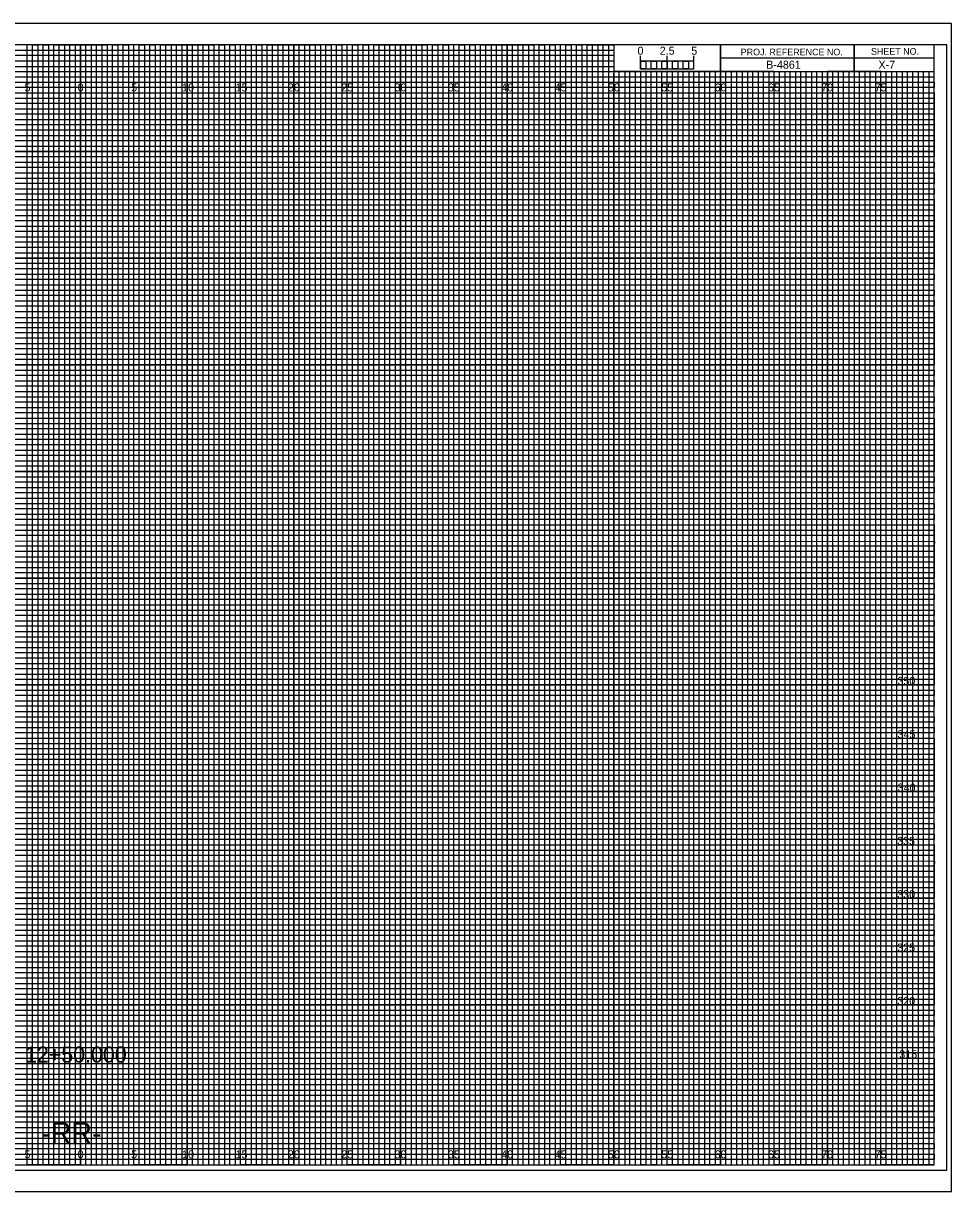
# Model space of a CAD drawing. Extents: x -7 to 162, y -2 to 327.
# Drawn here: x 74.6 to 161.7, y 217.5 to 327 of the extents above; entities that cross this region are included whole.
import ezdxf

# ---------------------------------------------------------------- set-up
doc = ezdxf.new("R2010")
doc.units = 0
for name, color, linetype in [('Exist Cross Section Cell', 7, 'Continuous'), ('Exist XS Center Line Elevation Label', 7, 'Continuous'), ('Exist XS Ground Line', 7, 'Continuous'), ('Old_Level_1', 7, 'Continuous'), ('Prop Retaining Wall', 7, 'Continuous'), ('Prop XS Bar Scale Labels', 7, 'Continuous'), ('Prop XS Bridge', 7, 'Continuous'), ('Prop XS Ditch Standard Text', 7, 'Continuous'), ('Prop XS EOT Tick Mark', 7, 'Continuous'), ('Prop XS Finish Grade Concrete', 7, 'Continuous'), ('Prop XS Finish Grade Earthwork', 7, 'Continuous'), ('Prop XS Label Text', 7, 'Continuous'), ('Prop XS SS Elevation Text', 7, 'Continuous'), ('Prop XS Subgrade', 7, 'Continuous'), ('Scratch_Level_3', 7, 'Continuous'), ('Scratch_Level_4', 7, 'Continuous'), ('Typical Arrow Superelevation CELL', 7, 'Continuous')]:
    doc.layers.add(name, color=color, linetype=linetype)

msp = doc.modelspace()

# ---------------------------------------------------------------- linework, layer by layer
at = {"layer": 'Exist XS Center Line Elevation Label'}
for points in [[(72.5, 220), (77.5, 220), (77.5, 325), (82.5, 325), (82.5, 220), (87.5, 220), (87.5, 325), (92.5, 325), (92.5, 220), (97.5, 220), (97.5, 325), (102.5, 325), (102.5, 220), (107.5, 220), (107.5, 325), (112.5, 325), (112.5, 220), (117.5, 220), (117.5, 325), (122.5, 325), (122.5, 220), (127.5, 220), (127.5, 325), (129.97, 325), (130, 325), (130, 322.5), (132.5, 322.5), (132.5, 220), (137.5, 220), (137.5, 322.5), (142.5, 322.5), (142.5, 220), (147.5, 220), (147.5, 322.5), (152.5, 322.5), (152.5, 220), (157.5, 220), (157.5, 322.5)], [(0, 322.5), (137.5, 322.5)], [(0, 312.5), (160, 312.5), (160, 317.5), (0, 317.5)], [(0, 302.5), (160, 302.5), (160, 307.5), (0, 307.5)], [(0, 292.5), (160, 292.5), (160, 297.5), (0, 297.5)], [(0, 282.5), (160, 282.5), (160, 287.5), (0, 287.5)], [(0, 272.5), (160, 272.5), (160, 277.5), (0, 277.5)], [(0, 262.5), (160, 262.5), (160, 267.5), (0, 267.5)], [(0, 252.5), (160, 252.5), (160, 257.5), (0, 257.5)], [(0, 242.5), (160, 242.5), (160, 247.5), (0, 247.5)], [(0, 232.5), (160, 232.5), (160, 237.5), (0, 237.5)], [(0, 222.5), (160, 222.5), (160, 227.5), (0, 227.5)]]:
    msp.add_lwpolyline(points, dxfattribs=at)
at = {"layer": 'Exist XS Ground Line'}
for p, q in [((75, 325), (70, 325)), ((75, 220), (75, 325)), ((85, 325), (80, 325)), ((80, 325), (80, 220)), ((85, 220), (85, 325)), ((95, 325), (90, 325)), ((90, 325), (90, 220)), ((95, 220), (95, 325)), ((105, 325), (100, 325)), ((100, 325), (100, 220)), ((105, 220), (105, 325)), ((115, 325), (110, 325)), ((110, 325), (110, 220)), ((115, 220), (115, 325)), ((125, 325), (120, 325)), ((120, 325), (120, 220)), ((125, 220), (125, 325)), ((130, 325), (130, 220)), ((135, 220), (135, 322.5)), ((145, 322.5), (140, 322.5)), ((140, 322.5), (140, 220)), ((145, 220), (145, 322.5)), ((155, 322.5), (150, 322.5)), ((150, 322.5), (150, 220)), ((155, 220), (155, 322.5)), ((80, 220), (75, 220)), ((90, 220), (85, 220)), ((100, 220), (95, 220)), ((110, 220), (105, 220)), ((120, 220), (115, 220)), ((130, 220), (125, 220)), ((140, 220), (135, 220)), ((150, 220), (145, 220)), ((160, 220), (155, 220)), ((160, 220), (160, 220))]:
    msp.add_line(p, q, dxfattribs=at)
for points in [[(0, 320), (160, 320), (160, 315), (0, 315)], [(0, 310), (160, 310), (160, 305), (0, 305)], [(0, 300), (160, 300), (160, 295), (0, 295)], [(0, 290), (160, 290), (160, 285), (0, 285)], [(0, 280), (160, 280), (160, 275), (0, 275)], [(0, 270), (160, 270), (160, 265), (0, 265)], [(0, 260), (160, 260), (160, 255), (0, 255)], [(0, 250), (160, 250), (160, 245), (0, 245)], [(0, 240), (160, 240), (160, 235), (0, 235)], [(0, 230), (160, 230), (160, 225), (0, 225)]]:
    msp.add_lwpolyline(points, dxfattribs=at)
at = {"layer": 'Old_Level_1'}
msp.add_lwpolyline([(-5.4, 219.5), (161.2, 219.5), (161.2, 325), (-5.4, 325)], close=True, dxfattribs=at)
at = {"layer": 'Prop XS Bridge'}
for p, q in [((75, 220), (75, 325)), ((80, 220), (80, 325)), ((85, 220), (85, 325)), ((90, 220), (90, 325)), ((95, 220), (95, 325)), ((100, 220), (100, 325)), ((105, 220), (105, 325)), ((110, 220), (110, 325)), ((115, 220), (115, 325)), ((120, 220), (120, 325)), ((125, 220), (125, 325)), ((130, 220), (130, 322.34)), ((135, 220), (135, 322.34)), ((140, 220), (140, 322.34)), ((145, 220), (145, 322.34)), ((150, 220), (150, 322.34)), ((155, 220), (155, 322.34)), ((0, 320), (160, 320)), ((0, 315), (160, 315)), ((0, 310), (160, 310)), ((0, 305), (160, 305)), ((0, 300), (160, 300)), ((0, 295), (160, 295)), ((0, 290), (160, 290)), ((0, 285), (160, 285)), ((0, 280), (160, 280)), ((0, 275), (160, 275)), ((0, 270), (160, 270)), ((0, 265), (160, 265)), ((0, 260), (160, 260)), ((0, 255), (160, 255)), ((0, 250), (160, 250)), ((0, 245), (160, 245)), ((0, 240), (160, 240)), ((0, 235), (160, 235)), ((0, 230), (160, 230)), ((0, 225), (160, 225))]:
    msp.add_line(p, q, dxfattribs=at)
at = {"layer": 'Prop XS EOT Tick Mark'}
for p, q in [((152.5, 325), (152.5, 322.5)), ((152.5, 322.5), (152.5, 325)), ((160, 323.75), (140, 323.75)), ((140, 323.75), (140, 322.5)), ((140, 322.5), (160, 322.5))]:
    msp.add_line(p, q, dxfattribs=at)
for points in [[(160, 325), (0, 325), (0, 220), (160, 220)], [(140, 325), (130, 325), (130, 322.51), (140, 322.51)], [(160, 325), (140, 325), (140, 322.5), (160, 322.5)]]:
    msp.add_lwpolyline(points, close=True, dxfattribs=at)
at = {"layer": 'Prop XS Finish Grade Earthwork'}
for p, q in [((161.65, 327), (-6.7, 327)), ((-6.7, 217.5), (161.65, 217.5))]:
    msp.add_line(p, q, dxfattribs=at)
at = {"layer": 'Prop XS Label Text'}
for p, q in [((133.5, 322.5), (133, 322.5)), ((133, 322.5), (133, 220)), ((133.5, 220), (133.5, 322.5)), ((134.5, 322.5), (134, 322.5)), ((134, 322.5), (134, 220)), ((134.5, 220), (134.5, 322.5)), ((133, 220), (132.5, 220)), ((134, 220), (133.5, 220))]:
    msp.add_line(p, q, dxfattribs=at)
for points in [[(75, 220), (75.5, 220), (75.5, 325), (76, 325), (76, 220)], [(76, 220), (76.5, 220), (76.5, 325), (77, 325), (77, 220)], [(77.5, 220), (78, 220), (78, 325), (78.5, 325), (78.5, 220)], [(78.5, 220), (79, 220), (79, 325), (79.5, 325), (79.5, 220)], [(80, 220), (80.5, 220), (80.5, 325), (81, 325), (81, 220)], [(81, 220), (81.5, 220), (81.5, 325), (82, 325), (82, 220)], [(82.5, 220), (83, 220), (83, 325), (83.5, 325), (83.5, 220)], [(83.5, 220), (84, 220), (84, 325), (84.5, 325), (84.5, 220)], [(85, 220), (85.5, 220), (85.5, 325), (86, 325), (86, 220)], [(86, 220), (86.5, 220), (86.5, 325), (87, 325), (87, 220)], [(87.5, 220), (88, 220), (88, 325), (88.5, 325), (88.5, 220)], [(88.5, 220), (89, 220), (89, 325), (89.5, 325), (89.5, 220)], [(90, 220), (90.5, 220), (90.5, 325), (91, 325), (91, 220)], [(91, 220), (91.5, 220), (91.5, 325), (92, 325), (92, 220)], [(92.5, 220), (93, 220), (93, 325), (93.5, 325), (93.5, 220)], [(93.5, 220), (94, 220), (94, 325), (94.5, 325), (94.5, 220)], [(95, 220), (95.5, 220), (95.5, 325), (96, 325), (96, 220)], [(96, 220), (96.5, 220), (96.5, 325), (97, 325), (97, 220)], [(97.5, 220), (98, 220), (98, 325), (98.5, 325), (98.5, 220)], [(98.5, 220), (99, 220), (99, 325), (99.5, 325), (99.5, 220)], [(100, 220), (100.5, 220), (100.5, 325), (101, 325), (101, 220)], [(101, 220), (101.5, 220), (101.5, 325), (102, 325), (102, 220)], [(102.5, 220), (103, 220), (103, 325), (103.5, 325), (103.5, 220)], [(103.5, 220), (104, 220), (104, 325), (104.5, 325), (104.5, 220)], [(105, 220), (105.5, 220), (105.5, 325), (106, 325), (106, 220)], [(106, 220), (106.5, 220), (106.5, 325), (107, 325), (107, 220)], [(107.5, 220), (108, 220), (108, 325), (108.5, 325), (108.5, 220)], [(108.5, 220), (109, 220), (109, 325), (109.5, 325), (109.5, 220)], [(110, 220), (110.5, 220), (110.5, 325), (111, 325), (111, 220)], [(111, 220), (111.5, 220), (111.5, 325), (112, 325), (112, 220)], [(112.5, 220), (113, 220), (113, 325), (113.5, 325), (113.5, 220)], [(113.5, 220), (114, 220), (114, 325), (114.5, 325), (114.5, 220)], [(115, 220), (115.5, 220), (115.5, 325), (116, 325), (116, 220)], [(116, 220), (116.5, 220), (116.5, 325), (117, 325), (117, 220)], [(117.5, 220), (118, 220), (118, 325), (118.5, 325), (118.5, 220)], [(118.5, 220), (119, 220), (119, 325), (119.5, 325), (119.5, 220)], [(120, 220), (120.5, 220), (120.5, 325), (121, 325), (121, 220)], [(121, 220), (121.5, 220), (121.5, 325), (122, 325), (122, 220)], [(122.5, 220), (123, 220), (123, 325), (123.5, 325), (123.5, 220)], [(123.5, 220), (124, 220), (124, 325), (124.5, 325), (124.5, 220)], [(125, 220), (125.5, 220), (125.5, 325), (126, 325), (126, 220)], [(126, 220), (126.5, 220), (126.5, 325), (127, 325), (127, 220)], [(127.5, 220), (128, 220), (128, 325), (128.5, 325), (128.5, 220)], [(128.5, 220), (129, 220), (129, 325), (129.5, 325), (129.5, 220)], [(130, 220), (130.5, 220), (130.5, 322.5), (131.01, 322.5), (131.01, 220)], [(131, 220), (131.5, 220), (131.5, 322.5), (132, 322.5), (132, 220)], [(135, 220), (135.49, 220), (135.49, 322.5), (136, 322.5), (136, 220)], [(136, 220), (136.5, 220), (136.5, 322.5), (137.03, 322.5), (137.03, 220)], [(137.5, 220), (138, 220), (138, 322.5), (138.5, 322.5), (138.5, 220)], [(138.5, 220), (139, 220), (139, 322.5), (139.5, 322.5), (139.5, 220)], [(140, 220), (140.5, 220), (140.5, 322.5), (141, 322.5), (141, 220)], [(141, 220), (141.5, 220), (141.5, 322.5), (142, 322.5), (142, 220)], [(142.5, 220), (143, 220), (143, 322.5), (143.5, 322.5), (143.5, 220)], [(143.5, 220), (144, 220), (144, 322.5), (144.5, 322.5), (144.5, 220)], [(145, 220), (145.5, 220), (145.5, 322.5), (146, 322.5), (146, 220)], [(146, 220), (146.5, 220), (146.5, 322.5), (147, 322.5), (147, 220)], [(147.5, 220), (148, 220), (148, 322.5), (148.5, 322.5), (148.5, 220)], [(148.5, 220), (149, 220), (149, 322.5), (149.5, 322.5), (149.5, 220)], [(150, 220), (150.5, 220), (150.5, 322.5), (151, 322.5), (151, 220)], [(151, 220), (151.5, 220), (151.5, 322.5), (152, 322.5), (152, 220)], [(152.5, 220), (153, 220), (153, 322.5), (153.5, 322.5), (153.5, 220)], [(153.5, 220), (154, 220), (154, 322.5), (154.5, 322.5), (154.5, 220)], [(155, 220), (155.5, 220), (155.5, 322.5), (156, 322.5), (156, 220)], [(156, 220), (156.5, 220), (156.5, 322.5), (157, 322.5), (157, 220)], [(157.5, 220), (158, 220), (158, 322.5), (158.5, 322.5), (158.5, 220)], [(158.5, 220), (159, 220), (159, 322.5), (159.5, 322.5), (159.5, 220)]]:
    msp.add_lwpolyline(points, dxfattribs=at)
at = {"layer": 'Prop XS Subgrade'}
msp.add_lwpolyline([(-6.7, 217.5), (161.65, 217.5), (161.65, 327), (-6.7, 327)], close=True, dxfattribs=at)
at = {"layer": 'Scratch_Level_3'}
for p, q in [((0, 324.5), (130, 324.5)), ((130, 324.5), (130, 323.99)), ((130, 323.99), (0, 323.99)), ((0, 323.5), (130, 323.5)), ((130, 323.5), (130, 322.94)), ((130, 322.94), (0, 322.94)), ((0, 322), (160, 322))]:
    msp.add_line(p, q, dxfattribs=at)
for points in [[(0, 321.5), (135, 321.5), (160, 321.5), (160, 321), (0, 321)], [(0, 320.5), (160, 320.5), (160, 319.5), (0, 319.5)], [(0, 319), (160, 319), (160, 318.5), (0, 318.49)], [(0, 318), (160, 318), (160, 317), (0, 317)], [(0, 316.5), (160, 316.5), (160, 316), (0, 316)], [(0, 315.5), (160, 315.5), (160, 314.5), (0, 314.5)], [(0, 314), (160, 314), (160, 313.5), (0, 313.5)], [(0, 313), (160, 313), (160, 312), (0, 312)], [(0, 311.5), (160, 311.5), (160, 311), (0, 311)], [(0, 310.5), (160, 310.5), (160, 309.5), (0, 309.5)], [(0, 309), (160, 309), (160, 308.5), (0, 308.5)], [(0, 308), (160, 308), (160, 306.98), (160, 306.5), (160, 306), (0, 306)], [(0, 307), (160, 307), (160, 306.5), (0, 306.5)], [(0, 305.5), (160, 305.5), (160, 304.5), (0, 304.51)], [(0, 304.51), (160, 304.5), (160, 304), (0, 304)], [(0, 303.5), (160, 303.5), (160, 303), (0, 303)], [(0, 302), (160, 302), (160, 301.5), (0, 301.5)], [(0, 301), (160, 301), (160, 300.5), (0, 300.5)], [(-0.04, 299.44), (160, 299.44), (160, 298.94), (-0.04, 298.94)], [(0, 298.5), (160, 298.5), (160, 298), (0, 298)], [(0, 297), (160, 297), (160, 296.5), (0, 296.5)], [(0, 296), (160, 296), (160, 295.5), (0, 295.5)], [(0, 294.5), (160, 294.5), (160, 294), (0, 294)], [(0, 293.5), (160, 293.5), (160, 293), (0, 293)], [(0, 292), (160, 292), (160, 291.5), (0, 291.5)], [(0, 291), (160, 291), (160, 290.5), (0, 290.5)], [(0, 289.5), (160, 289.5), (160, 288.99), (0, 289)], [(0, 288.5), (160, 288.5), (160, 288), (0, 288)], [(0, 287), (160, 287), (160, 286.5), (0, 286.5)], [(0, 286), (160, 286), (160, 285.5), (0, 285.5)], [(0, 284.5), (160, 284.5), (160, 284), (0, 284)], [(0, 283.5), (160, 283.5), (160, 283), (0, 283)], [(0, 282), (160, 282), (160, 281.5), (0, 281.5)], [(0, 281), (160, 281), (160, 280.5), (0, 280.5)], [(0, 279.5), (160, 279.5), (160, 279), (0, 279)], [(0, 278.5), (160.03, 278.45), (160, 278), (0, 278)], [(0, 277), (160, 277), (160, 276.5), (0, 276.5)], [(0, 276), (160, 276), (160, 275.5), (0, 275.5)], [(0, 274.5), (160, 274.5), (160, 274), (0, 274)], [(0, 273.5), (160, 273.5), (160, 273), (0, 273)], [(0, 272), (160, 272), (160, 271.5), (0, 271.5)], [(0, 271), (160, 271), (160, 270.5), (0, 270.5)], [(0, 269.5), (160, 269.5), (160, 269), (0, 269)], [(0, 268.5), (160, 268.5), (160, 268), (0, 268)], [(0, 267), (160, 267), (160, 266.5), (0, 266.5)], [(0, 266), (160, 266), (160, 265.5), (0, 265.5)], [(0, 264.5), (160, 264.5), (160, 264), (0, 264)], [(0, 263.5), (160, 263.5), (160, 263), (0, 263)], [(0, 262), (160, 262), (160, 261.5), (0, 261.5)], [(0, 261), (160, 261), (160, 260.5), (0, 260.5)], [(0, 259.5), (160, 259.5), (160, 258.99), (0, 259)], [(0, 258.5), (160, 258.5), (160, 258), (0, 258)], [(0, 257), (160, 257), (160, 256.5), (0, 256.5)], [(0, 256), (160, 256), (160, 255.5), (0, 255.5)], [(0, 254.5), (160, 254.5), (160, 254), (0, 254)], [(0, 253.5), (160, 253.5), (160, 253), (0, 253)], [(0, 252), (160, 252), (160, 251.5), (0, 251.5)], [(0, 251), (160, 251), (160, 250.5), (0, 250.5)], [(0, 249.5), (160, 249.5), (160, 249), (0, 249)], [(0, 248.5), (160.03, 248.46), (160, 248), (0, 248)], [(0, 247), (160, 247), (160, 246.5), (0, 246.5)], [(0, 246), (160, 246), (160, 245.5), (0, 245.5)], [(0, 244.5), (160, 244.5), (160, 244), (0, 244)], [(0, 243.5), (160, 243.5), (160, 243), (0, 243)], [(0, 242), (160, 242), (160, 241.5), (0, 241.5)], [(0, 241), (160, 241), (160, 240.5), (0, 240.5)], [(0, 239.5), (160, 239.5), (160, 239), (0, 239)], [(0, 238.5), (160, 238.5), (160, 238), (0, 238)], [(0, 237), (160, 237), (160, 236.5), (0, 236.5)], [(0, 236), (160, 236), (160, 235.5), (0, 235.5)], [(0, 234.5), (160, 234.5), (160, 234), (0, 234)], [(0, 233.5), (160, 233.5), (160, 233), (0, 233)], [(0, 232), (160, 232), (160, 231.5), (0, 231.5)], [(0, 231), (160, 231), (160, 230.5), (0, 230.5)], [(0, 229.5), (160, 229.5), (160, 229), (0, 229)], [(0, 228.5), (160, 228.5), (160, 228), (0, 228)], [(0, 227), (160, 227), (160, 226.5), (0, 226.5)], [(0, 226), (160, 226), (160, 225.5), (0, 225.5)], [(0, 224.5), (160, 224.5), (160, 224), (0, 224)], [(0, 223.5), (160, 223.5), (160, 223), (0, 223)], [(0, 222), (160, 222), (160, 221.5), (0, 221.5)], [(0, 221), (160, 221), (160, 220.5), (0, 220.5)]]:
    msp.add_lwpolyline(points, dxfattribs=at)
at = {"layer": 'Scratch_Level_4'}
for p, q in [((132.5, 322.75), (132.5, 323.95)), ((132.5, 323.45), (132.5, 323.95)), ((135, 322.75), (135, 323.95)), ((137.5, 322.75), (137.5, 323.95)), ((137.5, 323.45), (137.5, 323.95))]:
    msp.add_line(p, q, dxfattribs=at)
for points in [[(137.5, 323.45), (132.5, 323.45), (132.5, 322.75), (137.5, 322.75)], [(132.5, 323.45), (133, 323.45), (133, 322.75), (132.5, 322.75)], [(133.5, 323.45), (134, 323.45), (134, 322.75), (133.5, 322.75)], [(134.5, 323.45), (135, 323.45), (135, 322.75), (134.5, 322.75)], [(135.5, 323.45), (136, 323.45), (136, 322.75), (135.5, 322.75)], [(136.5, 323.45), (137, 323.45), (137, 322.75), (136.5, 322.75)]]:
    msp.add_lwpolyline(points, close=True, dxfattribs=at)

# ---------------------------------------------------------------- texts
at = {"layer": 'Exist Cross Section Cell'}
for s, p in [('5', (74.74, 320.62)), ('0', (79.73, 320.62)), ('0', (79.73, 320.62)), ('5', (84.74, 320.62)), ('10', (89.52, 320.62)), ('15', (94.53, 320.62)), ('20', (99.43, 320.62)), ('25', (104.44, 320.62)), ('30', (109.43, 320.62)), ('35', (114.44, 320.62)), ('40', (119.43, 320.62)), ('45', (124.44, 320.62)), ('50', (129.43, 320.62)), ('55', (134.44, 320.62)), ('60', (139.43, 320.62)), ('65', (144.44, 320.62)), ('70', (149.43, 320.62)), ('75', (154.44, 320.62)), ('5', (74.74, 220.62)), ('0', (79.73, 220.62)), ('0', (79.73, 220.62)), ('5', (84.74, 220.62)), ('10', (89.52, 220.62)), ('15', (94.53, 220.62)), ('20', (99.43, 220.62)), ('25', (104.44, 220.62)), ('30', (109.43, 220.62)), ('35', (114.44, 220.62)), ('40', (119.43, 220.62)), ('45', (124.44, 220.62)), ('50', (129.43, 220.62)), ('55', (134.44, 220.62)), ('60', (139.43, 220.62)), ('65', (144.44, 220.62)), ('70', (149.43, 220.62)), ('75', (154.44, 220.62))]:
    msp.add_text(s, height=0.75, dxfattribs=at).set_placement(p)
at = {"layer": 'Prop Retaining Wall'}
msp.add_text('-RR-', height=2, dxfattribs=at).set_placement((76.32, 222))
at = {"layer": 'Prop XS Bar Scale Labels'}
for s, p in [('2.5', (134.29, 324.06)), ('5', (137.24, 324.06))]:
    msp.add_text(s, height=0.75, dxfattribs=at).set_placement(p)
at = {"layer": 'Prop XS Ditch Standard Text'}
for s, p in [('350', (156.57, 265)), ('345', (156.58, 260)), ('340', (156.59, 255)), ('335', (156.54, 250)), ('330', (156.55, 245)), ('325', (156.55, 240)), ('320', (156.56, 235)), ('315', (156.74, 230))]:
    msp.add_text(s, height=0.75, dxfattribs=at).set_placement(p)
at = {"layer": 'Prop XS EOT Tick Mark'}
for s, p in [('PROJ. REFERENCE NO.', (141.88, 324)), ('SHEET NO.', (154.09, 324.06))]:
    msp.add_text(s, height=0.625, dxfattribs=at).set_placement(p)
at = {"layer": 'Prop XS Finish Grade Concrete'}
msp.add_text('12+50.000', height=1.5, dxfattribs=at).set_placement((74.79, 229.6))
at = {"layer": 'Prop XS SS Elevation Text'}
msp.add_text('B-4861', height=0.75, dxfattribs=at).set_placement((144.27, 322.75))
at = {"layer": 'Scratch_Level_4'}
msp.add_text('0', height=0.75, dxfattribs=at).set_placement((132.21, 324.06))
at = {"layer": 'Typical Arrow Superelevation CELL'}
msp.add_text('X-7', height=0.75, dxfattribs=at).set_placement((154.79, 322.75))

doc.saveas('drawing.dxf')
